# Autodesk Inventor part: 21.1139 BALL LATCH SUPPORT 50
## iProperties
Created: 2007-03
Part Number: 21.1139 BALL LATCH SUPPORT 50
Document SubType Name: Modeling
Designer: Andy Moles
Material: Aluminum-6061
Density: 2.71 g/cm^3
Author: Andy Moles
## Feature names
1. Base1
